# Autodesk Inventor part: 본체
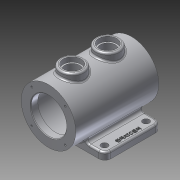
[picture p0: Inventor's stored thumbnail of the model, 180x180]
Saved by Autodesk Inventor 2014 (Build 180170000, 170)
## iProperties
Created: 2014-12
Part Number: 본체
Material: 알루미늄 6061
Document SubType Name: Modeling
Designer: Owner
Mass: 1293.91 g
Surface Area: 1040.15 cm^2
Volume: 477.456 cm^3
Density: 2.71 g/cm^3
Appearance: 알루미늄 - 평지
Author: Owner
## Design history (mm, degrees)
sketch "스케치1"
  geometry: C1 r 46 at (0, 0); 1 further point
  constraints: 1 centre point, 1 coincident
  dimensions: "d0" = 92 diameter of C1
extrude "돌출1" new body sketch "스케치1" distance "d1" = 140; taper "d2" = 0 deg
sketch "스케치2"
  geometry: C1 r 46 at (0, 0) reference; C2 r 30 at (0, 0)
  constraints: 1 centre point, 1 coincident
  dimensions: "d3" = 60 diameter of C2
extrude "돌출2" cut sketch "스케치2" distance "d4" = 12; taper "d5" = 0 deg
sketch "스케치3"
  geometry: C1 r 30 at (0, 0) reference; C2 r 37.5 at (0, 0)
  constraints: 1 centre point, 1 coincident
  dimensions: "d6" = 75 diameter of C2
extrude "돌출3" cut sketch "스케치3" distance "d7" = 116; taper "d8" = 0 deg
sketch "스케치4"
  geometry: C1 r 46 at (0, 0) reference; C2 r 30 at (0, 0)
  constraints: 1 centre point, 1 coincident
  dimensions: "d9" = 60 diameter of C2
extrude "돌출4" cut sketch "스케치4" distance "d10" = 12; taper "d11" = 0 deg
node "작업 평면1"
sketch "스케치5"
  geometry: L1 (-46, 0)-(46, 0) reference; L2 (65, 30)-(-65, 30); L3 (-65, 30)-(-65, 125); L4 (-65, 125)-(65, 125); L5 (65, 125)-(65, 30); 3 further points
  constraints: 8 end point, 2 midpoint, 2 parallel, 1 horizontal, 1 perpendicular, 1 vertical alignment
  dimensions: "d13" = 95 distance of L2.end L3.end; "d14" = 30 vertical distance of L2.end L1.start; "d15" = 130 distance of L2.end L2.start
extrude "돌출5" join sketch "스케치5" distance "d16" = 12; taper "d17" = 0 deg
node "작업 평면2"
sketch "스케치6"
  geometry: L1 (46, 140)-(-46, 140) reference; L2 (-46, 0)-(46, 0) reference; C1 r 20 at (0, 40); C2 r 20 at (0, 100); 1 further point
  constraints: 2 centre point, 2 vertical alignment
  dimensions: "d19" = 40 diameter of C1; "d20" = 40 diameter of C2; "d21" = 40 distance from line of L2 C1.centre; "d22" = 60 distance of C2.centre C1.centre
extrude "돌출6" join sketch "스케치6" stored distance "d23" = 12; taper "d24" = 0 deg
sketch "스케치7"
  geometry: C1 r 20 at (0, 0) reference; C2 r 15 at (0, 0); C3 r 20 at (0, 60) reference; C4 r 15 at (0, 60); 1 further point
  constraints: 2 centre point, 2 coincident
  dimensions: "d25" = 30 diameter of C2; "d26" = 30 diameter of C4
extrude "돌출7" cut sketch "스케치7" distance "d27" = 8; taper "d28" = 0 deg
sketch "스케치8"
  geometry: C1 r 15 at (0, 0) reference; C2 r 12.5 at (0, 0); 2 further points
  constraints: 1 centre point, 1 coincident, 1 other
  dimensions: "d29" = 25 diameter of C2
extrude "돌출8" cut sketch "스케치8" stored distance "d30" = 8; taper "d31" = 0 deg
sketch "스케치9"
  geometry: C1 r 15 at (0, 0) reference; C2 r 12.5 at (0, 0); 1 further point
  constraints: 1 centre point, 1 coincident
  dimensions: "d32" = 25 diameter of C2
extrude "돌출9" cut sketch "스케치9" stored distance "d33" = 8; taper "d34" = 0 deg
sketch "스케치10"
  geometry: L1 (0, 0)-(-28.284, 28.284); L2 (0, 0)-(40, 0); C1 r 46 at (0, 0) reference; 1 further point
  constraints: 4 end point, 1 coincident, 1 equal length, 1 horizontal
  dimensions: "d35" = 40 distance of L1.start L1.end; "d36" = 135 deg angle of L2 L1
hole "구멍1" sketch "스케치10" at (-28.284, 28.284) diameter "d37" = 3.242; stored, may be unused: countersink angle "d41" = 90 deg, drill point angle "d43" = 118 deg; dims "d38" = 8, "d39" = 4, "d40" = 2, "d42" = 10
sketch "스케치11"
  geometry: L1 (0, 0)-(28.284, 28.284); L2 (0, 0)-(40, 0); C1 r 46 at (0, 0) reference; 1 further point
  constraints: 4 end point, 1 coincident, 1 equal length, 1 horizontal
  dimensions: "d44" = 40 distance of L1.start L1.end; "d45" = 45 deg angle of L2 L1
hole "구멍2" sketch "스케치11" at (28.284, 28.284) diameter "d46" = 3.242; stored, may be unused: countersink angle "d50" = 90 deg, drill point angle "d52" = 118 deg; dims "d47" = 8, "d48" = 4, "d49" = 2, "d51" = 10
sketch "스케치12"
  geometry: C1 r 5.5 at (-52, 112.5); 2 further points
  constraints: 1 centre point
  dimensions: "d53" = 11 diameter of C1; "d54" = 13 horizontal distance of C1.centre point (-65, 125); "d55" = 12.5 vertical distance of C1.centre point (-65, 125)
extrude "돌출10" cut sketch "스케치12" stored distance "d56" = 8; taper "d57" = 0 deg
sketch "스케치13"
  geometry: C1 r 5.5 at (-52, 42.5); 2 further points
  constraints: 1 centre point
  dimensions: "d58" = 11 diameter of C1; "d59" = 12.5 vertical distance of point (-65, 30) C1.centre; "d60" = 13 horizontal distance of point (-65, 30) C1.centre
extrude "돌출11" cut sketch "스케치13" stored distance "d61" = 8; taper "d62" = 0 deg
sketch "스케치14"
  geometry: L1 (65, 30)-(65, 125) reference; C1 r 5.5 at (52, 42.5) reference; 2 further points
  constraints: 1 other
  dimensions: "d63" = 35 vertical distance of C1.centre point (57, 77.5); "d64" = 8 distance from line of L1 point (57, 77.5)
feature "엠보싱1" sketch "스케치14" dims "d65" = 1, "d66" = 0
fillet "모깎기1" dims "d67" = 5
fillet "모깎기2" dims "d68" = 10
fillet "모깎기3" dims "d69" = 3
fillet "모깎기4" dims "d70" = 3
chamfer "모따기1" distance "d71" = 1; stored, may be unused: second distance "d72" = 2, angle "d73" = 45 deg
fillet "모깎기5" dims "d74" = 3
node "솔리드1"
mirror "대칭1"
mirror "대칭2"
mirror "대칭3"
mirror "대칭4"
mirror "대칭5"
mirror "대칭6"
other parameters: "d18" = 56
